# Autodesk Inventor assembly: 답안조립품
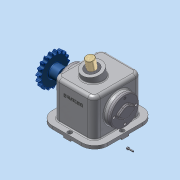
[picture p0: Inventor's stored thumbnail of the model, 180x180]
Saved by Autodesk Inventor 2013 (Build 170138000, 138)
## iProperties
Created: 2014-11
Part Number: 답안조립품
Document SubType Name: Assembly
Designer: WINDOWS7
Author: WINDOWS7
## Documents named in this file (13)
- C:\Users\WINDOWS7\Desktop\441123v1001\답안조립품.iam
- C:\Users\WINDOWS7\Desktop\441123v1001\5-체인 스프로킷.ipt
- C:\Users\WINDOWS7\Desktop\441123v1001\M4x0.5.ipt
- C:\Users\WINDOWS7\Desktop\441123v1001\뒤커버.ipt
- C:\Users\WINDOWS7\Desktop\441123v1001\멈춤나사 M5x0.5.ipt
- C:\Users\WINDOWS7\Desktop\441123v1001\베어링 6205.ipt
- C:\Users\WINDOWS7\Desktop\441123v1001\본체.ipt
- C:\Users\WINDOWS7\Desktop\441123v1001\부시.ipt
- C:\Users\WINDOWS7\Desktop\441123v1001\슬라이드.ipt
- C:\Users\WINDOWS7\Desktop\441123v1001\앞커버.ipt
- C:\Users\WINDOWS7\Desktop\441123v1001\오일실.ipt
- C:\Users\WINDOWS7\Desktop\441123v1001\키 8x8.ipt
- C:\Users\WINDOWS7\Desktop\441123v1001\편심축.ipt
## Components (3 placed, 2 different names)
1. 5-체인 스프로킷:1 — 플러쉬:1
2. M4x0.5:1
3. M4x0.5:2
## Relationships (1: Flush 1)
- 플러쉬:1 [Flush]: 5-체인 스프로킷:1
